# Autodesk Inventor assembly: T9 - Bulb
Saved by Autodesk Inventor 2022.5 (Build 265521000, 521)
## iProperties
Created: 2024-07
Part Number: T9 - Bulb
Document SubType Name: Assembly
Designer: AdminForWorker
Title: T9 - Bulb v3
Author: AdminForWorker
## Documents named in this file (2)
- c:\worker\convert-fusion-r03-cosv3\tmp\job-1\157\temp\files\32f11fbc-73c2-4b73-b173-800995eb16ca\T9 - Bulb v3.iam
- c:\worker\convert-fusion-r03-cosv3\tmp\job-1\157\temp\files\32f11fbc-73c2-4b73-b173-800995eb16ca\T9 - LED Bulb.iam
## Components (1 placed, 1 different names)
1. T9 - LED Bulb:1 [sub-assembly]
